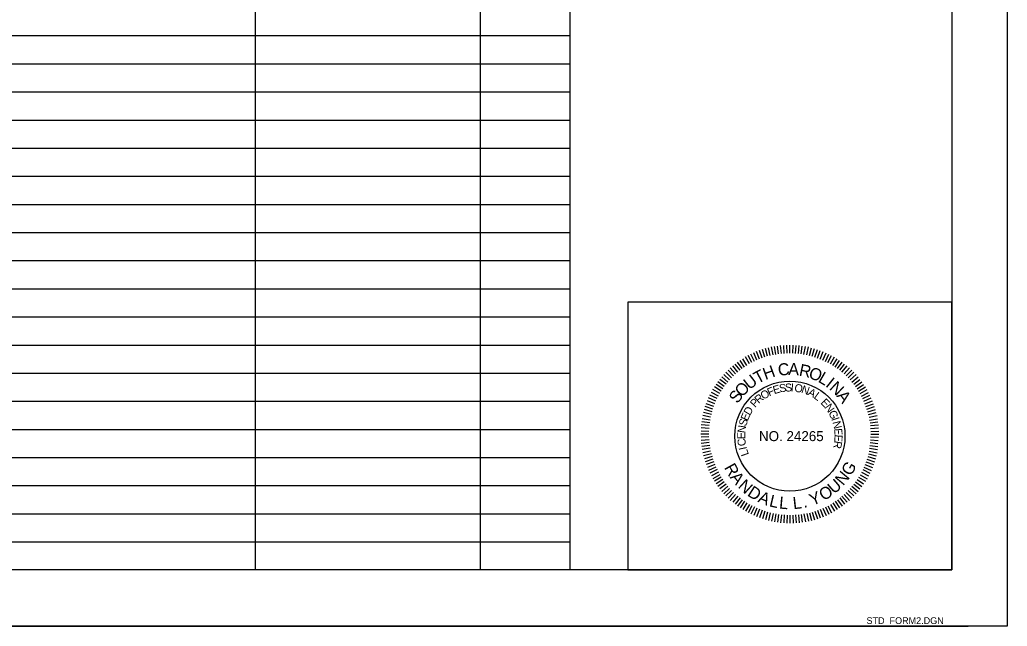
# Model space of a CAD drawing. Extents: x -796 to 2793, y -4650 to 4425.
# Drawn here: x 2338.3 to 2777.4, y -1250 to -980.4 of the extents above; entities that cross this region are included whole.
import ezdxf

# ---------------------------------------------------------------- set-up
doc = ezdxf.new("R2010")
doc.units = 0
for name, color, linetype in [('RD_EX_Misc', 7, 'Continuous'), ('RD_HC_CL', 7, 'Continuous'), ('RD_HC_Data', 7, 'Continuous'), ('RD_HC_Data_Tic', 7, 'Continuous')]:
    doc.layers.add(name, color=color, linetype=linetype)

msp = doc.modelspace()

# ---------------------------------------------------------------- linework, layer by layer
at = {"layer": 'RD_EX_Misc'}
for p, q in [((2666.09, -1131.69), (2664.64, -1128.44)), ((2666.09, -1131.69), (2664.64, -1128.44)), ((2667.26, -1131.24), (2665.93, -1127.95)), ((2667.26, -1131.24), (2665.93, -1127.95)), ((2668.44, -1130.79), (2667.22, -1127.45)), ((2668.44, -1130.79), (2667.22, -1127.45)), ((2669.61, -1130.34), (2668.51, -1126.96)), ((2669.61, -1130.34), (2668.51, -1126.96)), ((2670.83, -1130.02), (2669.85, -1126.6)), ((2670.83, -1130.02), (2669.85, -1126.6)), ((2672.04, -1129.69), (2671.18, -1126.24)), ((2672.04, -1129.69), (2671.18, -1126.24)), ((2673.26, -1129.36), (2672.52, -1125.88)), ((2673.26, -1129.36), (2672.52, -1125.88)), ((2674.5, -1129.17), (2673.88, -1125.67)), ((2674.5, -1129.17), (2673.88, -1125.67)), ((2675.74, -1128.97), (2675.24, -1125.45)), ((2675.74, -1128.97), (2675.24, -1125.45)), ((2676.98, -1128.77), (2676.61, -1125.23)), ((2676.98, -1128.77), (2676.61, -1125.23)), ((2678.24, -1128.71), (2677.99, -1125.16)), ((2678.24, -1128.71), (2677.99, -1125.16)), ((2679.49, -1128.64), (2679.37, -1125.09)), ((2679.49, -1128.64), (2679.37, -1125.09)), ((2680.75, -1128.58), (2680.75, -1125.02)), ((2680.75, -1128.58), (2680.75, -1125.02)), ((2682.01, -1128.64), (2682.13, -1125.09)), ((2682.01, -1128.64), (2682.13, -1125.09)), ((2683.26, -1128.71), (2683.51, -1125.16)), ((2683.26, -1128.71), (2683.51, -1125.16)), ((2684.52, -1128.77), (2684.89, -1125.23)), ((2684.52, -1128.77), (2684.89, -1125.23)), ((2685.76, -1128.97), (2686.26, -1125.45)), ((2685.76, -1128.97), (2686.26, -1125.45)), ((2687, -1129.17), (2687.62, -1125.67)), ((2687, -1129.17), (2687.62, -1125.67)), ((2688.24, -1129.36), (2688.98, -1125.88)), ((2688.24, -1129.36), (2688.98, -1125.88)), ((2688.24, -1129.36), (2688.98, -1125.88)), ((2689.46, -1129.69), (2690.32, -1126.24)), ((2689.46, -1129.69), (2690.32, -1126.24)), ((2689.46, -1129.69), (2690.32, -1126.24)), ((2690.67, -1130.02), (2691.65, -1126.6)), ((2690.67, -1130.02), (2691.65, -1126.6)), ((2690.67, -1130.02), (2691.65, -1126.6)), ((2691.89, -1130.34), (2692.99, -1126.96)), ((2691.89, -1130.34), (2692.99, -1126.96)), ((2691.89, -1130.34), (2692.99, -1126.96)), ((2693.06, -1130.79), (2694.28, -1127.45)), ((2693.06, -1130.79), (2694.28, -1127.45)), ((2693.06, -1130.79), (2694.28, -1127.45)), ((2694.24, -1131.24), (2695.57, -1127.95)), ((2694.24, -1131.24), (2695.57, -1127.95)), ((2694.24, -1131.24), (2695.57, -1127.95)), ((2695.41, -1131.69), (2696.86, -1128.44)), ((2695.41, -1131.69), (2696.86, -1128.44)), ((2695.41, -1131.69), (2696.86, -1128.44)), ((2659.56, -1135.46), (2657.47, -1132.58)), ((2659.56, -1135.46), (2657.47, -1132.58)), ((2660.62, -1134.78), (2658.63, -1131.83)), ((2660.62, -1134.78), (2658.63, -1131.83)), ((2661.67, -1134.09), (2659.79, -1131.08)), ((2661.67, -1134.09), (2659.79, -1131.08)), ((2662.73, -1133.41), (2660.95, -1130.32)), ((2662.73, -1133.41), (2660.95, -1130.32)), ((2663.85, -1132.83), (2662.18, -1129.7)), ((2663.85, -1132.83), (2662.18, -1129.7)), ((2664.97, -1132.26), (2663.41, -1129.07)), ((2664.97, -1132.26), (2663.41, -1129.07)), ((2696.53, -1132.26), (2698.09, -1129.07)), ((2696.53, -1132.26), (2698.09, -1129.07)), ((2696.53, -1132.26), (2698.09, -1129.07)), ((2697.65, -1132.83), (2699.32, -1129.7)), ((2697.65, -1132.83), (2699.32, -1129.7)), ((2697.65, -1132.83), (2699.32, -1129.7)), ((2698.77, -1133.41), (2700.55, -1130.32)), ((2698.77, -1133.41), (2700.55, -1130.32)), ((2698.77, -1133.41), (2700.55, -1130.32)), ((2699.83, -1134.09), (2701.71, -1131.08)), ((2699.83, -1134.09), (2701.71, -1131.08)), ((2699.83, -1134.09), (2701.71, -1131.08)), ((2700.88, -1134.78), (2702.87, -1131.83)), ((2700.88, -1134.78), (2702.87, -1131.83)), ((2700.88, -1134.78), (2702.87, -1131.83)), ((2701.94, -1135.46), (2704.03, -1132.58)), ((2701.94, -1135.46), (2704.03, -1132.58)), ((2701.94, -1135.46), (2704.03, -1132.58)), ((2654.85, -1139.61), (2652.3, -1137.14)), ((2654.85, -1139.61), (2652.3, -1137.14)), ((2655.74, -1138.72), (2653.27, -1136.17)), ((2655.74, -1138.72), (2653.27, -1136.17)), ((2656.63, -1137.84), (2654.25, -1135.19)), ((2656.63, -1137.84), (2654.25, -1135.19)), ((2657.61, -1137.04), (2655.32, -1134.32)), ((2657.61, -1137.04), (2655.32, -1134.32)), ((2658.59, -1136.25), (2656.4, -1133.45)), ((2658.59, -1136.25), (2656.4, -1133.45)), ((2702.91, -1136.25), (2705.1, -1133.45)), ((2702.91, -1136.25), (2705.1, -1133.45)), ((2702.91, -1136.25), (2705.1, -1133.45)), ((2703.89, -1137.04), (2706.18, -1134.32)), ((2703.89, -1137.04), (2706.18, -1134.32)), ((2703.89, -1137.04), (2706.18, -1134.32)), ((2704.87, -1137.84), (2707.25, -1135.19)), ((2704.87, -1137.84), (2707.25, -1135.19)), ((2704.87, -1137.84), (2707.25, -1135.19)), ((2705.76, -1138.72), (2708.23, -1136.17)), ((2705.76, -1138.72), (2708.23, -1136.17)), ((2705.76, -1138.72), (2708.23, -1136.17)), ((2706.65, -1139.61), (2709.2, -1137.14)), ((2706.65, -1139.61), (2709.2, -1137.14)), ((2706.65, -1139.61), (2709.2, -1137.14)), ((2651.59, -1143.44), (2648.71, -1141.34)), ((2651.59, -1143.44), (2648.71, -1141.34)), ((2652.38, -1142.46), (2649.58, -1140.27)), ((2652.38, -1142.46), (2649.58, -1140.27)), ((2653.17, -1141.48), (2650.45, -1139.2)), ((2653.17, -1141.48), (2650.45, -1139.2)), ((2653.96, -1140.5), (2651.32, -1138.12)), ((2653.96, -1140.5), (2651.32, -1138.12)), ((2707.54, -1140.5), (2710.18, -1138.12)), ((2707.54, -1140.5), (2710.18, -1138.12)), ((2707.54, -1140.5), (2710.18, -1138.12)), ((2708.33, -1141.48), (2711.05, -1139.2)), ((2708.33, -1141.48), (2711.05, -1139.2)), ((2708.33, -1141.48), (2711.05, -1139.2)), ((2709.12, -1142.46), (2711.92, -1140.27)), ((2709.12, -1142.46), (2711.92, -1140.27)), ((2709.12, -1142.46), (2711.92, -1140.27)), ((2709.91, -1143.44), (2712.79, -1141.34)), ((2709.91, -1143.44), (2712.79, -1141.34)), ((2709.91, -1143.44), (2712.79, -1141.34)), ((2648.96, -1147.72), (2645.82, -1146.05)), ((2648.96, -1147.72), (2645.82, -1146.05)), ((2649.53, -1146.6), (2646.45, -1144.82)), ((2649.53, -1146.6), (2646.45, -1144.82)), ((2650.22, -1145.54), (2647.2, -1143.66)), ((2650.22, -1145.54), (2647.2, -1143.66)), ((2650.9, -1144.49), (2647.96, -1142.5)), ((2650.9, -1144.49), (2647.96, -1142.5)), ((2710.6, -1144.49), (2713.54, -1142.5)), ((2710.6, -1144.49), (2713.54, -1142.5)), ((2710.6, -1144.49), (2713.54, -1142.5)), ((2711.28, -1145.54), (2714.3, -1143.66)), ((2711.28, -1145.54), (2714.3, -1143.66)), ((2711.28, -1145.54), (2714.3, -1143.66)), ((2711.97, -1146.6), (2715.05, -1144.82)), ((2711.97, -1146.6), (2715.05, -1144.82)), ((2711.97, -1146.6), (2715.05, -1144.82)), ((2712.54, -1147.72), (2715.68, -1146.05)), ((2712.54, -1147.72), (2715.68, -1146.05)), ((2712.54, -1147.72), (2715.68, -1146.05)), ((2647.37, -1151.14), (2644.07, -1149.8)), ((2647.37, -1151.14), (2644.07, -1149.8)), ((2647.82, -1149.96), (2644.57, -1148.51)), ((2647.82, -1149.96), (2644.57, -1148.51)), ((2648.39, -1148.84), (2645.2, -1147.28)), ((2648.39, -1148.84), (2645.2, -1147.28)), ((2713.11, -1148.84), (2716.3, -1147.28)), ((2713.11, -1148.84), (2716.3, -1147.28)), ((2713.11, -1148.84), (2716.3, -1147.28)), ((2713.68, -1149.96), (2716.93, -1148.51)), ((2713.68, -1149.96), (2716.93, -1148.51)), ((2713.68, -1149.96), (2716.93, -1148.51)), ((2714.13, -1151.14), (2717.43, -1149.8)), ((2714.13, -1151.14), (2717.43, -1149.8)), ((2714.13, -1151.14), (2717.43, -1149.8)), ((2646.14, -1154.7), (2642.73, -1153.72)), ((2646.14, -1154.7), (2642.73, -1153.72)), ((2646.47, -1153.48), (2643.08, -1152.38)), ((2646.47, -1153.48), (2643.08, -1152.38)), ((2646.92, -1152.31), (2643.58, -1151.09)), ((2646.92, -1152.31), (2643.58, -1151.09)), ((2714.58, -1152.31), (2717.92, -1151.09)), ((2714.58, -1152.31), (2717.92, -1151.09)), ((2714.58, -1152.31), (2717.92, -1151.09)), ((2715.03, -1153.48), (2718.42, -1152.38)), ((2715.03, -1153.48), (2718.42, -1152.38)), ((2715.03, -1153.48), (2718.42, -1152.38)), ((2715.36, -1154.7), (2718.77, -1153.72)), ((2715.36, -1154.7), (2718.77, -1153.72)), ((2715.36, -1154.7), (2718.77, -1153.72)), ((2645.1, -1159.61), (2641.58, -1159.12)), ((2645.1, -1159.61), (2641.58, -1159.12)), ((2645.3, -1158.37), (2641.79, -1157.75)), ((2645.3, -1158.37), (2641.79, -1157.75)), ((2645.49, -1157.13), (2642.01, -1156.39)), ((2645.49, -1157.13), (2642.01, -1156.39)), ((2645.82, -1155.91), (2642.37, -1155.05)), ((2645.82, -1155.91), (2642.37, -1155.05)), ((2715.68, -1155.91), (2719.13, -1155.05)), ((2715.68, -1155.91), (2719.13, -1155.05)), ((2715.68, -1155.91), (2719.13, -1155.05)), ((2716.01, -1157.13), (2719.49, -1156.39)), ((2716.01, -1157.13), (2719.49, -1156.39)), ((2716.01, -1157.13), (2719.49, -1156.39)), ((2716.2, -1158.37), (2719.71, -1157.75)), ((2716.2, -1158.37), (2719.71, -1157.75)), ((2716.2, -1158.37), (2719.71, -1157.75)), ((2716.4, -1159.61), (2719.92, -1159.12)), ((2716.4, -1159.61), (2719.92, -1159.12)), ((2716.4, -1159.61), (2719.92, -1159.12)), ((2644.77, -1163.37), (2641.22, -1163.24)), ((2644.77, -1163.37), (2641.22, -1163.24)), ((2644.84, -1162.11), (2641.29, -1161.86)), ((2644.84, -1162.11), (2641.29, -1161.86)), ((2644.9, -1160.85), (2641.36, -1160.48)), ((2644.9, -1160.85), (2641.36, -1160.48)), ((2716.6, -1160.85), (2720.14, -1160.48)), ((2716.6, -1160.85), (2720.14, -1160.48)), ((2716.6, -1160.85), (2720.14, -1160.48)), ((2716.66, -1162.11), (2720.21, -1161.86)), ((2716.66, -1162.11), (2720.21, -1161.86)), ((2716.66, -1162.11), (2720.21, -1161.86)), ((2716.73, -1163.37), (2720.28, -1163.24)), ((2716.73, -1163.37), (2720.28, -1163.24)), ((2716.73, -1163.37), (2720.28, -1163.24)), ((2644.71, -1164.62), (2641.15, -1164.62)), ((2644.71, -1164.62), (2641.15, -1164.62)), ((2644.77, -1165.88), (2641.22, -1166)), ((2644.77, -1165.88), (2641.22, -1166)), ((2644.84, -1167.13), (2641.29, -1167.38)), ((2644.84, -1167.13), (2641.29, -1167.38)), ((2716.53, -1167.12), (2720.07, -1167.37)), ((2716.53, -1167.12), (2720.07, -1167.37)), ((2716.66, -1165.88), (2720.21, -1166)), ((2716.66, -1165.88), (2720.21, -1166)), ((2716.8, -1164.62), (2720.36, -1164.62)), ((2716.8, -1164.62), (2720.36, -1164.62)), ((2716.8, -1164.62), (2720.36, -1164.62)), ((2644.9, -1168.39), (2641.36, -1168.76)), ((2644.9, -1168.39), (2641.36, -1168.76)), ((2645.1, -1169.63), (2641.58, -1170.13)), ((2645.1, -1169.63), (2641.58, -1170.13)), ((2645.3, -1170.87), (2641.79, -1171.49)), ((2645.3, -1170.87), (2641.79, -1171.49)), ((2645.49, -1172.12), (2642.01, -1172.86)), ((2645.49, -1172.12), (2642.01, -1172.86)), ((2716.01, -1172.12), (2719.49, -1172.86)), ((2716.01, -1172.12), (2719.49, -1172.86)), ((2716.14, -1170.86), (2719.63, -1171.48)), ((2716.14, -1170.86), (2719.63, -1171.48)), ((2716.27, -1169.61), (2719.78, -1170.11)), ((2716.27, -1169.61), (2719.78, -1170.11)), ((2716.4, -1168.37), (2719.92, -1168.74)), ((2716.4, -1168.37), (2719.92, -1168.74)), ((2645.82, -1173.33), (2642.37, -1174.19)), ((2645.82, -1173.33), (2642.37, -1174.19)), ((2646.14, -1174.55), (2642.73, -1175.53)), ((2646.14, -1174.55), (2642.73, -1175.53)), ((2646.47, -1175.76), (2643.08, -1176.86)), ((2715.03, -1175.76), (2718.42, -1176.86)), ((2715.03, -1175.76), (2718.42, -1176.86)), ((2715.36, -1174.55), (2718.77, -1175.53)), ((2715.36, -1174.55), (2718.77, -1175.53)), ((2715.68, -1173.33), (2719.13, -1174.19)), ((2715.68, -1173.33), (2719.13, -1174.19)), ((2646.92, -1176.94), (2643.58, -1178.15)), ((2646.92, -1176.94), (2643.58, -1178.15)), ((2647.37, -1178.11), (2644.07, -1179.44)), ((2647.37, -1178.11), (2644.07, -1179.44)), ((2647.82, -1179.28), (2644.57, -1180.73)), ((2647.82, -1179.28), (2644.57, -1180.73)), ((2648.39, -1180.4), (2645.2, -1181.96)), ((2648.39, -1180.4), (2645.2, -1181.96)), ((2713.11, -1180.4), (2716.3, -1181.96)), ((2713.11, -1180.4), (2716.3, -1181.96)), ((2713.68, -1179.28), (2716.93, -1180.73)), ((2713.68, -1179.28), (2716.93, -1180.73)), ((2714.13, -1178.11), (2717.43, -1179.44)), ((2714.13, -1178.11), (2717.43, -1179.44)), ((2714.58, -1176.94), (2717.92, -1178.15)), ((2714.58, -1176.94), (2717.92, -1178.15)), ((2648.96, -1181.52), (2645.82, -1183.19)), ((2648.96, -1181.52), (2645.82, -1183.19)), ((2649.53, -1182.64), (2646.45, -1184.42)), ((2649.53, -1182.64), (2646.45, -1184.42)), ((2650.22, -1183.7), (2647.2, -1185.58)), ((2650.22, -1183.7), (2647.2, -1185.58)), ((2650.9, -1184.75), (2647.96, -1186.74)), ((2650.9, -1184.75), (2647.96, -1186.74)), ((2710.6, -1184.75), (2713.54, -1186.74)), ((2710.6, -1184.75), (2713.54, -1186.74)), ((2711.28, -1183.7), (2714.3, -1185.58)), ((2711.28, -1183.7), (2714.3, -1185.58)), ((2711.97, -1182.64), (2715.05, -1184.42)), ((2711.97, -1182.64), (2715.05, -1184.42)), ((2712.54, -1181.52), (2715.68, -1183.19)), ((2712.54, -1181.52), (2715.68, -1183.19)), ((2651.59, -1185.81), (2648.71, -1187.9)), ((2651.59, -1185.81), (2648.71, -1187.9)), ((2652.38, -1186.79), (2649.58, -1188.98)), ((2652.38, -1186.79), (2649.58, -1188.98)), ((2653.17, -1187.76), (2650.45, -1190.05)), ((2653.17, -1187.76), (2650.45, -1190.05)), ((2653.96, -1188.74), (2651.32, -1191.12)), ((2653.96, -1188.74), (2651.32, -1191.12)), ((2654.85, -1189.63), (2652.3, -1192.1)), ((2654.85, -1189.63), (2652.3, -1192.1)), ((2706.65, -1189.63), (2709.2, -1192.1)), ((2706.65, -1189.63), (2709.2, -1192.1)), ((2707.54, -1188.74), (2710.18, -1191.12)), ((2707.54, -1188.74), (2710.18, -1191.12)), ((2708.33, -1187.76), (2711.05, -1190.05)), ((2708.33, -1187.76), (2711.05, -1190.05)), ((2709.12, -1186.79), (2711.92, -1188.98)), ((2709.12, -1186.79), (2711.92, -1188.98)), ((2709.91, -1185.81), (2712.79, -1187.9)), ((2709.91, -1185.81), (2712.79, -1187.9)), ((2655.74, -1190.52), (2653.27, -1193.08)), ((2655.74, -1190.52), (2653.27, -1193.08)), ((2656.63, -1191.41), (2654.25, -1194.05)), ((2656.63, -1191.41), (2654.25, -1194.05)), ((2657.61, -1192.2), (2655.32, -1194.92)), ((2657.61, -1192.2), (2655.32, -1194.92)), ((2658.59, -1192.99), (2656.4, -1195.79)), ((2658.59, -1192.99), (2656.4, -1195.79)), ((2659.56, -1193.78), (2657.47, -1196.66)), ((2659.56, -1193.78), (2657.47, -1196.66)), ((2701.94, -1193.78), (2704.03, -1196.66)), ((2701.94, -1193.78), (2704.03, -1196.66)), ((2702.91, -1192.99), (2705.1, -1195.79)), ((2702.91, -1192.99), (2705.1, -1195.79)), ((2703.89, -1192.2), (2706.18, -1194.92)), ((2703.89, -1192.2), (2706.18, -1194.92)), ((2704.87, -1191.41), (2707.25, -1194.05)), ((2705.76, -1190.52), (2708.23, -1193.08)), ((2705.76, -1190.52), (2708.23, -1193.08)), ((2660.62, -1194.47), (2658.63, -1197.42)), ((2660.62, -1194.47), (2658.63, -1197.42)), ((2661.67, -1195.15), (2659.79, -1198.17)), ((2661.67, -1195.15), (2659.79, -1198.17)), ((2662.73, -1195.84), (2660.95, -1198.92)), ((2662.73, -1195.84), (2660.95, -1198.92)), ((2663.85, -1196.41), (2662.18, -1199.55)), ((2663.85, -1196.41), (2662.18, -1199.55)), ((2664.97, -1196.98), (2663.41, -1200.18)), ((2664.97, -1196.98), (2663.41, -1200.18)), ((2666.09, -1197.55), (2664.64, -1200.8)), ((2666.09, -1197.55), (2664.64, -1200.8)), ((2667.26, -1198), (2665.93, -1201.3)), ((2667.26, -1198), (2665.93, -1201.3)), ((2668.44, -1198.45), (2667.22, -1201.79)), ((2668.44, -1198.45), (2667.22, -1201.79)), ((2693.06, -1198.45), (2694.28, -1201.79)), ((2693.06, -1198.45), (2694.28, -1201.79)), ((2694.24, -1198), (2695.57, -1201.3)), ((2694.24, -1198), (2695.57, -1201.3)), ((2695.41, -1197.55), (2696.86, -1200.8)), ((2695.41, -1197.55), (2696.86, -1200.8)), ((2696.53, -1196.98), (2698.09, -1200.18)), ((2696.53, -1196.98), (2698.09, -1200.18)), ((2697.65, -1196.41), (2699.32, -1199.55)), ((2697.65, -1196.41), (2699.32, -1199.55)), ((2698.77, -1195.84), (2700.55, -1198.92)), ((2698.77, -1195.84), (2700.55, -1198.92)), ((2699.83, -1195.15), (2701.71, -1198.17)), ((2699.83, -1195.15), (2701.71, -1198.17)), ((2700.88, -1194.47), (2702.87, -1197.42)), ((2700.88, -1194.47), (2702.87, -1197.42)), ((2669.61, -1198.9), (2668.51, -1202.29)), ((2669.61, -1198.9), (2668.51, -1202.29)), ((2670.83, -1199.23), (2669.85, -1202.65)), ((2670.83, -1199.23), (2669.85, -1202.65)), ((2672.04, -1199.55), (2671.18, -1203)), ((2672.04, -1199.55), (2671.18, -1203)), ((2673.26, -1199.88), (2672.52, -1203.36)), ((2673.26, -1199.88), (2672.52, -1203.36)), ((2674.5, -1200.08), (2673.88, -1203.58)), ((2674.5, -1200.08), (2673.88, -1203.58)), ((2675.74, -1200.27), (2675.24, -1203.79)), ((2675.74, -1200.27), (2675.24, -1203.79)), ((2676.98, -1200.47), (2676.61, -1204.01)), ((2676.98, -1200.47), (2676.61, -1204.01)), ((2678.24, -1200.54), (2677.99, -1204.08)), ((2678.24, -1200.54), (2677.99, -1204.08)), ((2679.49, -1200.6), (2679.37, -1204.15)), ((2679.49, -1200.6), (2679.37, -1204.15)), ((2680.75, -1200.67), (2680.75, -1204.23)), ((2680.75, -1200.67), (2680.75, -1204.23)), ((2682.01, -1200.6), (2682.13, -1204.15)), ((2682.01, -1200.6), (2682.13, -1204.15)), ((2683.26, -1200.54), (2683.51, -1204.08)), ((2683.26, -1200.54), (2683.51, -1204.08)), ((2684.52, -1200.47), (2684.89, -1204.01)), ((2684.52, -1200.47), (2684.89, -1204.01)), ((2685.76, -1200.27), (2686.26, -1203.79)), ((2685.76, -1200.27), (2686.26, -1203.79)), ((2687, -1200.08), (2687.62, -1203.58)), ((2687, -1200.08), (2687.62, -1203.58)), ((2688.24, -1199.88), (2688.98, -1203.36)), ((2688.24, -1199.88), (2688.98, -1203.36)), ((2689.46, -1199.55), (2690.32, -1203)), ((2689.46, -1199.55), (2690.32, -1203)), ((2690.67, -1199.23), (2691.65, -1202.65)), ((2690.67, -1199.23), (2691.65, -1202.65)), ((2691.89, -1198.9), (2692.99, -1202.29)), ((2691.89, -1198.9), (2692.99, -1202.29))]:
    msp.add_line(p, q, dxfattribs=at)
msp.add_circle((2680.75, -1165.5), 24.48, dxfattribs=at)
at = {"layer": 'RD_HC_CL'}
msp.add_lwpolyline([(981.41, -150), (2777.4, -150), (2777.4, -1250), (981.41, -1250)], close=True, dxfattribs=at)
at = {"layer": 'RD_HC_Data'}
for p, q in [((2442.95, -250), (2442.95, -1225)), ((2542.95, -250), (2542.95, -1225)), ((2582.95, -250), (2582.95, -1225)), ((1932.95, -987.5), (2582.95, -987.5)), ((1932.95, -1000), (2582.95, -1000)), ((1932.95, -1012.5), (2582.95, -1012.5)), ((1932.95, -1025), (2582.95, -1025)), ((1932.95, -1037.5), (2582.95, -1037.5)), ((1932.95, -1050), (2582.95, -1050)), ((1932.95, -1062.5), (2582.95, -1062.5)), ((1932.95, -1075), (2582.95, -1075)), ((1932.95, -1087.5), (2582.95, -1087.5)), ((1932.95, -1100), (2582.95, -1100)), ((1932.95, -1112.5), (2582.95, -1112.5)), ((1932.95, -1125), (2582.95, -1125)), ((1932.95, -1137.5), (2582.95, -1137.5)), ((1932.95, -1150), (2582.95, -1150)), ((1932.95, -1162.5), (2582.95, -1162.5)), ((1932.95, -1175), (2582.95, -1175)), ((1932.95, -1187.5), (2582.95, -1187.5)), ((1932.95, -1200), (2582.95, -1200)), ((1932.95, -1212.5), (2582.95, -1212.5)), ((2760, -1250), (1000, -1250)), ((1000, -1250), (2760, -1250))]:
    msp.add_line(p, q, dxfattribs=at)
for points in [[(1077.75, -175), (2752.75, -175), (2752.75, -1225), (1077.75, -1225)], [(2608.75, -1225), (2752.75, -1225), (2752.75, -1106), (2608.75, -1106)]]:
    msp.add_lwpolyline(points, close=True, dxfattribs=at)

# ---------------------------------------------------------------- texts
at = {"layer": 'RD_EX_Misc'}
for s, height, rotation, p in [('T', 5.34, 28.0947, (2666.41, -1142.38)), ('H', 5.34, 19.9102, (2669.85, -1140.58)), ('C', 5.34, 6.8832, (2675.74, -1138.76)), ('A', 5.34, 357.9448, (2679.96, -1138.31)), ('R', 5.34, 348.267, (2684.54, -1138.56)), ('O', 5.34, 339.3286, (2688.68, -1139.48)), ('L', 5.34, 329.6507, (2692.94, -1141.18)), ('U', 5.34, 37.7726, (2662.73, -1145.12)), ('I', 5.34, 321.4663, (2696.28, -1143.17)), ('N', 5.34, 317.0007, (2697.97, -1144.44)), ('S', 5.34, 54.9027, (2657.53, -1151.34)), ('O', 5.34, 47.4504, (2659.56, -1148.44)), ('O', 3.56, 31.7869, (2668.99, -1149.44)), ('F', 3.56, 23.0853, (2671.56, -1147.84)), ('E', 3.56, 16.1843, (2673.75, -1146.87)), ('S', 3.56, 8.6909, (2676.24, -1146.11)), ('S', 3.56, 1.79, (2678.6, -1145.71)), ('I', 3.56, 354.889, (2680.99, -1145.6)), ('O', 3.56, 350.4045, (2682.55, -1145.68)), ('N', 3.56, 341.7029, (2685.53, -1146.18)), ('A', 3.56, 333.0013, (2688.4, -1147.12)), ('L', 3.56, 324.2997, (2691.09, -1148.49)), ('A', 5.34, 307.3229, (2701.27, -1147.64)), ('P', 3.56, 46.7912, (2665.24, -1153.03)), ('R', 3.56, 39.8902, (2666.85, -1151.25)), ('E', 3.56, 313.2251, (2694.16, -1150.79)), ('D', 3.56, 59.074, (2662.94, -1156.61)), ('N', 3.56, 305.7317, (2695.97, -1152.67)), ('G', 3.56, 297.0301, (2697.73, -1155.12)), ('S', 3.56, 73.4683, (2661.29, -1161.32)), ('E', 3.56, 66.5674, (2661.93, -1159.01)), ('I', 3.56, 288.3285, (2699.11, -1157.81)), ('N', 3.56, 283.8441, (2699.65, -1159.26)), ('N', 3.56, 82.17, (2660.88, -1164.31)), ('E', 3.56, 275.1424, (2700.38, -1162.2)), ('E', 3.56, 89.6633, (2660.89, -1166.91)), ('C', 3.56, 97.7667, (2661.29, -1169.7)), ('R', 3.56, 260.1557, (2700.57, -1167.39)), ('E', 3.56, 267.6491, (2700.64, -1164.78)), ('I', 3.56, 102.2511, (2661.68, -1171.21)), ('L', 3.56, 109.7445, (2662.59, -1173.65)), ('R', 5.34, 299.1493, (2651.35, -1179.47)), ('N', 5.34, 50.4335, (2704.44, -1187.82)), ('G', 5.34, 60.1113, (2707.86, -1183.52)), ('A', 5.34, 308.0877, (2653.88, -1183.87)), ('N', 5.34, 317.7655, (2657.35, -1188.13)), ('U', 5.34, 40.7556, (2700.35, -1191.49)), ('D', 5.34, 327.4433, (2661.48, -1191.74)), ('Y', 5.34, 21.4, (2690.63, -1196.52)), ('O', 5.34, 31.0778, (2695.71, -1194.42)), ('A', 5.34, 337.1212, (2666.17, -1194.61)), ('L', 5.34, 346.799, (2671.27, -1196.64)), ('L', 5.34, 354.9835, (2675.8, -1197.68)), ('L', 5.34, 6.5171, (2682.33, -1198.02)), ('.', 5.34, 14.7016, (2686.95, -1197.46))]:
    msp.add_text(s, height=height, rotation=rotation, dxfattribs=at).set_placement(p)
msp.add_text('NO. 24265', height=4.45, dxfattribs=at).set_placement((2667, -1167.73))
at = {"layer": 'RD_HC_Data_Tic'}
msp.add_text('STD_FORM2.DGN', height=3, dxfattribs=at).set_placement((2714.82, -1249.01))

doc.saveas('drawing.dxf')
